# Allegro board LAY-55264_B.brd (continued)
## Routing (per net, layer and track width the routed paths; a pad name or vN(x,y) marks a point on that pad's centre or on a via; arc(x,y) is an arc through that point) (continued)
VCC_1V0_SER: length 20.6
  TOP w0.254: U1.23 31.7,51.69 v2(31.24,51.69) 30.86,51.69 TP18.1
  TOP w0.381: R22.1 16.21,65.61 18.44,63.37 v2(18.44,57.91)
  TOP w0.508: C30.1 v2(20.98,50.19) ; C30.1 v2(20.98,53.98) ; C30.1 v2(22.73,52.07)
  BOTTOM w0.381: C28.1 31.24,51.18 v2(31.24,51.69)
  BOTTOM w0.508: C29.1 v2(31.24,51.69)
  vias: v2(16.93,55.86) v2(17.7,57.1) v2(18.06,55.85) v2(19.23,56.9) v2(19.23,55.83)
VCC_1V8_LVDS: length 71.4
  TOP w0.254: U4.6 95.92,51.68 95.92,52.05 v2(95.85,52.13) ; v2(97.64,50.33) 97.4,50.33 U4.2 ; 134.24,9.02 v2(135,9.02) ; 134.24,6.48 v2(134.24,7.23) ; v2(89.11,52.92) U4.20 ; v2(98.27,49.7) 97.48,49.7 U4.1 ; U4.5 96.36,51.41 96.39,51.41 v2(96.48,51.5) ; R112.2 v2(80.25,55.88) ; U4.43 92.87,43.5 v2(92.87,42.89) 92.87,42.53 92.96,42.44 TP22.1 ; U4.44 v2(93.55,43.53) ; 134.24,3.94 v2(134.24,4.69)
  TOP w0.279: v2(134.36,45.3) 134.15,45.09 U6.39 ; U6.17 v2(138.97,38.12)
  TOP w0.381: R40.1 v2(97.13,57.36) ; R36.1 v2(78.14,48.03) ; TP23.1 98.97,50.04 98.61,50.04 v2(98.27,49.7) ; R73.2 v2(86.51,29.55) ; C50.2 v2(93.63,40.65)
  TOP w0.508: v2(129.79,12.2) 131.15,13.55 v2(131.15,13.91) 129.68,15.38 v2(127.89,15.38) 126.38,15.38 125.73,14.73 117.6,14.73 115.57,16.76 115.57,18.07 v2(114.72,18.92) ; R39.1 v2(95.73,39.95)
  L3_MIX_1 w0.508: 74.3,35.24 J6.28 ; J6.28 73.34,36.2 ; J6.28 75.25,36.2 ; J6.28 74.3,37.15 ; J6.29 72.71,33.66 ; J6.29 71.75,32.7 ; J6.29 70.8,33.66 ; J6.29 71.75,34.61 ; J6.27 71.75,37.15 ; J6.27 71.75,35.24 ; J6.27 72.71,36.2 ; J6.27 70.8,36.2 ; J6.30 74.3,34.61 ; J6.30 75.25,33.66 ; J6.30 74.3,32.7 ; J6.30 73.34,33.66 ; J12.3 71.75,29.02 ; J12.3 70.67,27.94 ; J12.3 72.84,27.94
  BOTTOM w0.381: C51.1 93.55,43.65 v2(93.55,43.53) ; C52.1 v2(92.87,42.89) ; C53.1 96.48,51.14 v2(96.48,51.5) ; C55.1 89.72,52.31 v2(89.11,52.92) ; C41.1 97.1,50.33 v2(97.64,50.33) ; R76.2 v2(98.17,26.3) ; R77.2 v2(95.81,26.3) ; C54.1 95.85,51.95 v2(95.85,52.13) ; R41.1 v2(86.69,56.44) ; C40.1 97.91,49.7 v2(98.27,49.7)
  BOTTOM w0.508: R92.2 v2(131.15,13.91) ; R46.1 v2(127.89,15.38) ; R45.1 v2(129.79,12.2)
  vias: v1(89.29,41.1) v1(90.22,40.18) v2(89.46,19.79) v2(89.46,18.92) v2(113.64,20.18) v2(132.82,52.95) v2(132.82,51.87) v2(132.82,50.61) v2(132.84,53.98) v2(132.97,55.04) v2(133.9,53.95) v2(135,55.02) v2(134.98,53.95)
VCC_1V8_MIPI: length 52.1
  TOP w0.254: R88.2 v2(53.47,40.37) ; v1(34.46,52.11) 34.11,52.11 U1.19 ; U9.5 v2(52.07,53.1) ; U1.28 30.2,49.66 29.54,49.66 v2(29.29,49.4) ; U1.9 v2(38.46,52.85)
  TOP w0.381: v2(29.29,49.4) 28.75,48.87 TP19.1 ; v2(48.13,28.22) 48.16,28.19 TP49.1 ; U2.5 31.61,34.91 31.62,34.92 v2(32.37,34.92) ; U3.1 v2(15.9,63.84) ; R100.1 v2(20.95,70.24) ; R98.1 v2(20.95,67.7) ; R108.1 v2(20.95,72.77)
  TOP w0.508: 49.3,57.97 v2(49.83,58.5) ; R23.1 v2(50.53,45.26) ; R18.1 v2(48.38,59.96) ; R24.1 v2(50.53,49.58) ; R16.1 v2(45.15,56.05)
  L3_MIX_1 w0.508: J4.27 4.44,37.15 ; J4.27 3.49,36.2 ; J4.27 5.4,36.2 ; J4.27 4.44,35.24 ; 6.98,32.7 J4.30 ; J4.30 7.94,33.66 ; J4.30 6.03,33.66 ; J4.30 6.98,34.61 ; 6.03,36.2 J4.28 ; J4.28 6.98,37.15 ; J4.28 7.94,36.2 ; J4.28 6.98,35.24 ; 4.44,32.7 J4.29 ; J4.29 5.4,33.66 ; J4.29 3.49,33.66 ; J4.29 4.44,34.61
  BOTTOM w0.381: v2(33.4,30.45) 32.88,30.98 U8.5
  BOTTOM w0.508: C21.1 35.07,52.73 35.07,52.73 v1(34.46,52.11) ; C23.1 39.01,53.41 v2(38.46,52.85) 37.91,52.31 C22.1 ; C24.1 30.14,49.4 v2(29.29,49.4) 29.29,49.41 C25.1 ; R14.1 v2(36.83,30.62)
  BOTTOM w0.635: J11.3 58.42,22.86 53.21,28.07 C1.2
  vias: v2(11.51,56.74) v2(12,57.83) v2(12.72,56.83) v2(22.87,28.04) v2(23.83,27.19) v2(48.13,27.41)
VCC_3V3_LVDS: length 54
  TOP w0.254: 143.64,33.78 v2(144.39,33.78) ; v2(144.39,32.77) 143.64,32.77
  TOP w0.279: U6.23 140.79,41.12 v2(140.97,41.3) ; U6.4 134.15,35.32 v1(133.49,34.65) ; U6.9 v2(136.65,35.52)
  TOP w0.381: U5.5 v2(79.42,45.45) ; U7.5 v2(77.2,53.58)
  TOP w0.508: D3.A v2(143.28,12.58) ; D4.A v2(143.28,10.17) ; D9.A v2(143.26,14.99) ; R74.1 v2(141.62,36.7) ; D13.A v2(143.26,17.41)
  L3_MIX_1 w0.381: v2(77.2,53.58) 77.2,47.68 v2(79.42,45.45)
  L3_MIX_1 w0.508: J12.1 71.75,23.94 ; J12.1 70.67,22.86 ; J12.1 72.84,22.86 ; J12.1 71.75,21.78
  BOTTOM w0.381: C105.1 140.18,41.3 v2(140.97,41.3) ; v2(79.42,45.45) 79.42,44.7 C42.2 79.32,42.47 77.95,41.1 77.95,33.07 74.04,29.16 74.04,23.24 73.66,22.86 J12.1
  BOTTOM w0.508: R49.1 v2(132.89,19.86)
  vias: v1(136.53,22.35) v1(142.62,39.5) v2(83.06,19.79) v2(83.06,18.92) v2(108.32,19.79) v2(108.32,18.92) v2(135.38,28.32) v2(135.38,27.3) v2(135.38,26.42) v2(135.38,25.4) v2(135.38,24.26) v2(135.38,23.24) v2(135.38,22.35) v2(136.53,28.32) v2(136.53,27.18) v2(136.53,26.29) v2(136.53,25.27) v2(136.53,24.26) v2(136.53,23.24) v2(137.67,23.24) v2(137.67,22.35) v2(138.81,23.24) v2(138.81,22.35)
VCC_3V3_MIPI: length 10.6
  TOP w0.381: v2(41.68,28.19) TP50.1
  TOP w0.508: D7.A v2(61.72,41.54) ; D14.A v2(61.72,43.96) ; D2.A v2(61.72,36.06) ; D1.A v2(61.72,38.48)
  L4_MIX_2 w0.508: 60.13,28.77 J11.1 ; J11.1 61.79,27.11 ; J11.1 60.13,27.11 ; J11.1 61.79,28.77
  BOTTOM w0.508: R28.1 v2(54.28,44.7)
  vias: v2(14.73,34.42) v2(14.73,32.26) v2(15.61,33.53) v2(41.7,27.2)
VCC_5V0_LVDS: length 7.5
  TOP w0.254: v1(135.12,34.89) 135.15,34.92 U6.6 ; U6.48 131.16,41.12 v2(130.94,40.89) ; U6.36 135.65,45.1 v2(135.89,45.34) ; v2(134.06,37.37) 133.65,36.96 U6.3 ; U6.53 v2(132.83,38.62)
  TOP w0.508: D11.A v2(143.37,19.4)
  BOTTOM w0.254: C100.1 v2(135.89,45.34)
  vias: v1(112.9,56.77) v1(135.36,33.63) v1(135.99,32.97) v2(79.07,19.79) v2(79.1,18.92) v2(104.33,19.79) v2(104.36,18.92) v2(110.97,56.77) v2(110.97,55.63) v2(110.97,54.48) v2(110.97,53.47) v2(111.89,56.77) v2(111.94,55.63) v2(112.01,54.57) v2(112.9,55.63) v2(112.9,54.23) v2(113.92,55.4) v2(114.94,55.4) v2(115.9,55.4) v2(136.3,46.63) v2(137.13,46.65)
VCC_5V0_MIPI: length 1.8
  TOP w0.508: TP51.1 37.97,27.69 38.48,27.18 v2(39.21,27.18)
  vias: v2(13.93,28.17) v2(14.94,27.19) v2(39.2,28.17)
VCC_12V0: length 5
  TOP w0.635: J9.2 122.44,73.53 ; J9.2 124.2,71.76 ; J9.2 122.44,71.76 ; J9.2 124.2,73.53
VCC_12V0_DESCONN: length 6.9
  TOP w0.635: 120.78,71.49 J9.3 ; J9.3 119.62,72.64 ; J9.3 120.78,73.8
  BOTTOM w0.635: 120.78,71.49 J9.3 ; J9.3 120.78,73.8 ; J9.3 119.62,72.64
  vias: v2(110.24,68.07) v2(110.92,67.24) v2(110.98,68.85) v2(111.76,69.6) v2(112.52,70.36) v2(113.18,69.49)
VCC_12V0_EXT: length 18
  TOP w0.508: 137.32,60.46 J10.1 ; J10.1 138.71,61.85 ; J10.1 137.32,63.23 ; J10.1 135.93,61.85
  TOP w0.635: J9.1 127.01,72.64 ; J9.1 125.86,73.8 ; J9.1 125.86,71.49
  BOTTOM w0.508: J10.1 138.71,61.85 ; J10.1 135.93,61.85 ; J10.1 137.32,60.46 ; J10.1 137.32,63.23
  BOTTOM w0.635: 125.86,71.49 J9.1 ; J9.1 125.86,73.8 ; J9.1 127.01,72.64
  vias: v2(130.18,65.15) v2(130.18,64.14) v2(130.18,62.99) v2(131.19,62.99) v2(132.46,62.99) v2(133.6,62.99)
VCC_12V0_LVDS: length 20.8
  TOP w0.381: R57.1 v2(112.66,41.27)
  TOP w0.508: D10.A v2(143.37,21.05)
  BOTTOM w0.381: v2(143.37,21.05) 142.71,21.72 132.33,21.72 131.7,21.08 130.3,21.08 129.54,21.84 v2(125.22,21.84)
  vias: v2(85.47,19.79) v2(85.5,18.92) v2(110.73,19.79) v2(110.76,18.92) v2(114.17,63.12) v2(114.17,62.1) v2(114.81,65.02) v2(114.81,64.01) v2(115.19,63.12) v2(115.19,62.1) v2(115.82,65.02) v2(115.82,64.01) v2(116.2,63.12) v2(116.2,62.1) v2(116.84,65.02) v2(116.84,64.01) v2(117.22,63.12) v2(117.22,62.1) v2(118.24,63.12) v2(118.24,62.1) v2(119.25,63.12) v2(119.25,62.1) v2(123.83,25.27) v2(123.83,24.13) v2(123.83,22.99) v2(123.83,21.84) v2(123.83,20.7) v2(125.09,25.27) v2(125.22,24.13) v2(125.22,22.99) v2(125.22,20.7) v2(126.24,25.27) v2(126.49,20.7) v2(127,28.58) v2(127,27.56) v2(127,26.54) v2(127.51,25.27)
VCC_12V0_MIPI: length 11.5
  TOP w0.381: TP52.1 20.37,27.18 v2(20.4,27.2)
  TOP w0.508: 57.47,59.56 C86.1 ; C86.1 59.88,59.56 ; C86.1 58.67,58.36 ; C86.1 58.67,60.77 ; D8.A v2(61.72,46.39)
  L3_MIX_1 w0.508: C86.1 58.67,60.69 ; C86.1 59.81,59.56 ; C86.1 58.67,58.43 ; C86.1 57.54,59.56
  vias: v2(20.41,28.19) v2(45.67,28.19) v2(45.66,27.2) v2(56.9,62.61) v2(56.9,61.47) v2(58.17,62.61) v2(58.17,61.47) v2(59.44,62.61) v2(59.44,61.47) v2(60.45,60.83) v2(60.45,59.69) v2(60.45,58.67) v2(60.58,61.98) v2(61.72,60.83) v2(61.72,59.69) v2(61.72,58.67)
VCC_12V0_SER: length 32.2
  TOP w0.254: TP16.1 v2(53.98,71.25)
  TOP w0.508: D12.A v2(60.72,49.64)
  L3_MIX_1 w0.254: v2(53.21,65.6) 54.74,67.12 54.74,70.48 v2(53.98,71.25)
  BOTTOM w0.381: v2(52.2,64.77) 52.2,56.39 51.18,55.37 51.18,51.69 51.94,50.93 59.43,50.93 v2(60.72,49.64)
  vias: v2(51.18,66.67) v2(51.18,65.71) v2(51.18,64.77) v2(51.69,67.44) v2(52.2,66.67) v2(52.2,65.71) v2(53.21,64.77)
VDDA_MAX96752: length 5
  TOP w0.254: v2(94.68,53.3) 94.68,53.27 U4.10
  TOP w0.381: TP2.1 95.25,53.72 95.1,53.72 v2(94.68,53.3)
  BOTTOM w0.381: C48.2 95.31,53.92 v2(94.68,53.3) C49.1
VDDD_MAX96752: length 5.9
  TOP w0.254: U4.56 97.6,47.97 98.06,47.97
  TOP w0.381: 98.06,47.97 99.46,47.97 C47.1 C46.2 TP1.1
FS84_DBG: length 9.6
  TOP w0.254: U6.8 v2(136.15,37.29)
  TOP w0.381: R79.2 v2(139.84,31.5)
  BOTTOM w0.381: v2(139.84,31.5) 139.84,34.53 138.43,35.94 137.5,35.94 v2(136.15,37.29)
FS84_ERRMON: length 2
  TOP w0.137: U6.40 133.65,45.25 v2(133.54,45.35)
  BOTTOM w0.137: v2(133.54,45.35) 133.6,45.42 R64.1
FS84_INTB: length 4.1
  TOP w0.137: C98.1 139.07,47.12 139.07,46.74 137.15,44.82 U6.33
FS84_PRE_BOOT: length 3.1
  TOP w0.137: C79.2 130.04,41.78 130.94,41.78 131.27,42.12 U6.46
FS84_PRE_COMP: length 3.6
  TOP w0.254: U6.41 133.15,44.95 132.84,45.26 132.84,45.72 R63.1 C85.1
FS84_PRE_CSP: length 14.1
  TOP w0.254: v2(132.23,45.14) 132.65,44.72 U6.42
  BOTTOM w0.381: v2(132.23,45.14) 132.23,45.95 125.25,52.93 v2(125.25,55.32)
FS84_PRE_GHS: length 7.8
  TOP w0.254: U6.45 131.01,42.62 130.92,42.53 v1(130.31,42.53)
  TOP w0.381: Q7.2 125.24,42.53 v2(125.6,42.16)
  BOTTOM w0.381: v1(130.31,42.53) 129.95,42.16 v2(125.6,42.16)
FS84_PRE_GLS: length 9
  TOP w0.254: v2(125.46,45.07) 125.45,45.07 Q7.4 ; U6.43 131.41,43.62 v2(131.09,43.94)
  BOTTOM w0.381: v2(131.09,43.94) 129.17,43.94 127.89,45.21 125.61,45.21 v2(125.46,45.07) 125.45,45.07 124.73,45.07 R61.1
FS84_PRE_SW: length 2.8
  TOP w0.254: C79.1 R60.1 130.74,43.12 U6.44
FS84_PSYNC: length 2.8
  TOP w0.254: U6.38 134.65,43.53 v2(134.75,43.43)
  BOTTOM w0.254: v2(134.75,43.43) C94.1 R62.2
FS84_SCL: length 5.7
  TOP w0.137: R65.2 139.52,33.83 139.52,34.38 138.77,35.13 137.72,35.13 137.15,35.7 U6.10
FS84_SDA: length 4.5
  TOP w0.137: U6.11 137.65,35.7 137.96,35.39 138.88,35.39 140.51,33.76 R66.2
FS84_VBOS: length 5.6
  TOP w0.254: U6.47 v2(132.83,41.62)
  BOTTOM w0.254: v2(132.83,41.62) 131.83,42.62 R62.1 131.83,44.2 131.44,44.58 130.94,44.58 C78.2
FS84_WAKE1: length 24.9
  TOP w0.137: C74.1 R58.2 v2(113.41,45.07) ; U6.49 v2(132.83,40.62)
  BOTTOM w0.137: v2(132.83,40.62) 131.58,39.37 126.87,39.37 121.18,45.07 v2(113.41,45.07)
GMSL2_OUT0_N: length 19.7
  TOP w0.114: C10.1 30.19,54.61 arc(30.16,54.74) 30.09,54.84 30.08,54.85 arc(29.97,54.92) 29.85,54.95 v1(29.58,54.95)
  BOTTOM w0.114: v1(29.58,54.95) 28.11,56.42 arc(27.98,56.62) 27.93,56.84 27.93,58 arc(27.7,58.56) 27.14,58.79 26.82,58.79 arc(26.13,59.08) 25.84,59.77 25.84,60.67 arc(26.11,61.31) 26.75,61.57 26.87,61.57 arc(27.61,61.88) 27.92,62.63 27.92,69.16 arc(27.79,69.48) 27.47,69.61 J3.4
GMSL2_OUT0_P: length 19.7
  TOP w0.114: C9.1 30.5,54.96 arc(30.39,54.99) 30.3,55.05 30.28,55.06 arc(30.22,55.15) 30.2,55.26 v1(30.2,55.57)
  BOTTOM w0.114: v1(30.2,55.57) 29.44,55.57 arc(29.38,55.58) 29.32,55.62 28.31,56.63 arc(28.25,56.73) 28.22,56.84 28.22,58 arc(27.91,58.77) 27.14,59.08 26.82,59.08 arc(26.34,59.28) 26.13,59.77 26.13,60.67 arc(26.32,61.1) 26.75,61.28 26.87,61.28 arc(27.82,61.68) 28.21,62.63 28.21,69.15 arc(28.35,69.48) 28.67,69.61 J3.3
GMSL2_OUT1_N: length 19.7
  TOP w0.114: v1(41.73,54.4) 41.44,54.4 arc(41.32,54.37) 41.23,54.31 41.21,54.29 arc(41.15,54.2) 41.12,54.08 C12.1
  BOTTOM w0.114: J3.1 36.63,69.61 arc(36.33,69.49) 36.21,69.2 36.21,63.21 arc(36.34,62.57) 36.7,62.03 42.1,56.63 arc(42.28,56.36) 42.35,56.04 42.35,55.21 arc(42.3,55) 42.17,54.83 v1(41.73,54.4)
GMSL2_OUT1_P: length 19.7
  TOP w0.114: C11.1 40.79,54.41 arc(40.91,54.44) 41,54.5 41.02,54.52 arc(41.08,54.61) 41.11,54.73 v1(41.11,55.02)
  BOTTOM w0.114: J3.2 35.5,69.61 arc(35.8,69.49) 35.92,69.2 35.92,63.21 arc(36.07,62.46) 36.49,61.83 41.9,56.42 arc(42.01,56.25) 42.06,56.04 42.06,55.21 arc(42,55.08) 41.86,55.02 v1(41.11,55.02)
GMSL2DES_OUT0_N: length 20.2
  TOP w0.114: v1(84.22,55.13) 84.49,55.13 arc(84.62,55.11) 84.74,55.03 85.27,54.5 arc(85.34,54.39) 85.37,54.26 C35.1
  BOTTOM w0.114: v1(84.22,55.13) 83.34,56.01 arc(83.16,56.27) 83.1,56.58 83.1,57.41 arc(82.92,57.85) 82.47,58.04 82.36,58.04 arc(81.83,58.26) 81.61,58.78 81.61,59.02 arc(81.87,59.63) 82.47,59.88 arc(82.92,60.06) 83.1,60.51 83.1,60.79 arc(83.24,61.46) 83.62,62.04 85.21,63.63 arc(85.59,64.2) 85.73,64.87 85.73,69.27 arc(85.63,69.51) 85.38,69.61 J5.4
GMSL2DES_OUT0_P: length 20.2
  TOP w0.114: v1(84.86,55.77) 84.86,55.5 arc(84.88,55.37) 84.96,55.26 85.45,54.77 arc(85.56,54.69) 85.69,54.67 C34.1
  BOTTOM w0.114: v1(84.86,55.77) 84.26,55.77 arc(84.01,55.82) 83.8,55.96 83.54,56.22 arc(83.43,56.38) 83.39,56.58 83.39,57.41 arc(83.12,58.06) 82.47,58.33 82.36,58.33 arc(82.04,58.46) 81.91,58.78 81.91,59.02 arc(82.07,59.42) 82.47,59.59 arc(83.12,59.86) 83.39,60.51 83.39,60.79 arc(83.51,61.35) 83.83,61.83 85.42,63.42 arc(85.86,64.09) 86.02,64.87 86.02,69.27 arc(86.12,69.51) 86.36,69.61 J5.3
GMSL2DES_OUT1_N: length 21.6
  TOP w0.114: v1(99.84,53.19) 99.56,53.19 arc(99.43,53.17) 99.32,53.09 99.09,52.86 arc(99.02,52.75) 98.99,52.62 C37.1
  BOTTOM w0.114: J5.1 94.19,69.61 arc(94.07,69.56) 94.02,69.44 94.02,65.81 arc(94.47,63.55) 95.75,61.64 100.35,57.03 arc(100.67,56.57) 100.78,56.01 100.78,54.52 arc(100.7,54.15) 100.49,53.84 v1(99.84,53.19)
GMSL2DES_OUT1_P: length 21.6
  TOP w0.114: C36.1 98.58,52.94 arc(98.71,52.96) 98.82,53.04 99.1,53.32 arc(99.18,53.43) 99.2,53.56 v1(99.2,53.83)
  BOTTOM w0.114: J5.2 93.61,69.61 arc(93.69,69.58) 93.73,69.5 93.73,65.81 arc(94.2,63.44) 95.54,61.43 100.15,56.83 arc(100.4,56.45) 100.48,56.01 100.48,54.52 arc(100.43,54.27) 100.29,54.05 100.17,53.93 arc(100.06,53.86) 99.93,53.83 v1(99.2,53.83)
LDO_1V0_FB_SER: length 2.8
  TOP w0.137: U3.3 12.9,64.57 R27.1 R22.2
LVDS0_BL_PWM: length 59.2
  TOP w0.137: v2(83.44,49.42) R114.2
  L4_MIX_2 w0.14: v2(84.02,28.27) 86.25,26.04 v2(87.02,26.04) 87.02,26.57 88.67,28.22 98.55,28.22 v2(100.36,26.42)
  BOTTOM w0.137: v2(84.02,28.27) 83.36,28.93 83.36,30.66 84.76,32.05 84.76,44.32 84.28,44.81 84.28,47.6 83.44,48.44 v2(83.44,49.42) ; J7.B8 v2(87.02,26.04) ; v2(100.36,26.42) 104.8,30.86 111.63,30.86 R52.2
LVDS0_CH0_CLK_N: length 36.5
  TOP w0.114: U4.35 88.56,45.73 88.41,45.73 85.23,42.55 85.23,26.44 89.57,22.11 89.73,22.11 89.88,22.25 90.04,22.25 90.2,22.09 90.2,21.93 90.05,21.78 90.05,21.62 90.21,21.46 90.37,21.46 90.52,21.61 90.68,21.61 90.85,21.45 90.85,21.28 90.7,21.14 90.7,20.97 91.16,20.51 91.16,20.07 91.67,19.55 91.93,19.55 v2(92.22,19.85)
  BOTTOM w0.114: J7.A2 91.42,20.89 91.15,20.61 91.15,19.82 91.43,19.55 91.92,19.55 v2(92.22,19.85)
LVDS0_CH0_CLK_P: length 36.5
  TOP w0.114: v2(92.22,18.97) 91.93,19.26 91.55,19.26 90.87,19.94 90.87,20.39 84.94,26.32 84.94,42.67 88.2,45.94 88.2,46.09 U4.34
  BOTTOM w0.114: v2(92.22,18.97) 91.94,19.25 91.27,19.25 90.86,19.67 90.86,20.6 90.62,20.83 J7.A3
LVDS0_CH0_TS_SCL: length 30.8
  BOTTOM w0.137: J16.3 95.28,13.3 95.28,17.7 93.68,19.3 93.68,28.04 92.79,28.93 86.16,28.93 84.62,27.4 J7.B11
LVDS0_CH0_TS_SDA: length 34.2
  BOTTOM w0.137: J7.B10 85.42,27.61 86.36,28.55 92.72,28.55 93.36,27.91 93.36,19.17 94.96,17.57 94.96,13.09 95.63,12.42 95.63,11.05 96.37,10.31 98.25,10.31 J16.4
LVDS0_CH0_TX0_N: length 36.6
  TOP w0.114: v2(91.87,27.68) 91.57,27.97 91.57,28.35 91.83,28.61 91.83,28.88 91.57,29.14 91.57,31.84 91.68,31.96 93.42,31.96 93.71,32.24 93.71,32.94 93.42,33.23 91.68,33.23 91.57,33.34 91.57,33.8 91.68,33.91 93.42,33.91 93.71,34.2 93.71,34.9 93.42,35.18 91.68,35.18 91.57,35.3 91.57,35.76 91.68,35.87 93.42,35.87 93.71,36.16 93.71,36.85 93.42,37.14 91.68,37.14 91.57,37.25 91.57,38.19 91,38.76 88.16,38.76 88.04,38.88 88.04,41.29 89.02,42.27 89.02,43.52 89.83,44.32 89.97,44.32 U4.39
  BOTTOM w0.114: v2(91.87,27.68) 91.58,27.39 91.58,25.81 91.82,25.57 J7.B2
LVDS0_CH0_TX0_P: length 36.6
  TOP w0.114: U4.38 89.62,44.67 89.62,44.52 88.73,43.64 88.73,42.39 87.75,41.41 87.75,38.76 88.04,38.47 90.87,38.47 91.28,38.07 91.28,37.13 91.56,36.85 93.3,36.85 93.41,36.73 93.41,36.28 93.3,36.16 91.56,36.16 91.28,35.88 91.28,35.18 91.56,34.89 93.3,34.89 93.41,34.78 93.41,34.32 93.3,34.21 91.56,34.21 91.28,33.92 91.28,33.22 91.56,32.94 93.3,32.94 93.41,32.82 93.41,32.36 93.3,32.25 91.56,32.25 91.28,31.97 91.28,27.97 v2(90.98,27.68)
  BOTTOM w0.114: v2(90.98,27.68) 91.29,27.37 91.29,25.83 91.02,25.57 J7.B3
LVDS0_CH0_TX1_N: length 36.5
  TOP w0.114: v2(89.47,26.66) 89.12,27.01 89.12,27.35 89.32,27.55 89.32,27.93 89.12,28.13 89.12,30.37 88.75,30.74 88.75,30.9 89.67,31.82 89.67,32.22 89.18,32.72 88.78,32.72 87.86,31.8 87.69,31.8 86.73,32.76 86.73,33.78 86.84,33.9 89.07,33.9 89.36,34.18 89.36,34.88 89.07,35.17 86.84,35.17 86.73,35.28 86.73,35.74 86.84,35.85 89.07,35.85 89.36,36.14 89.36,36.84 89.07,37.12 86.84,37.12 86.73,37.24 86.73,42.02 88.15,43.44 88.15,44.06 89.12,45.02 89.27,45.02 U4.37
  BOTTOM w0.114: v2(89.47,26.66) 89.17,26.36 89.17,25.83 89.42,25.57 J7.B5
LVDS0_CH0_TX1_P: length 36.5
  TOP w0.114: U4.36 88.91,45.38 88.91,45.23 87.86,44.18 87.86,43.56 86.44,42.14 86.44,37.12 86.72,36.83 88.95,36.83 89.07,36.72 89.07,36.26 88.95,36.14 86.72,36.14 86.44,35.86 86.44,35.16 86.72,34.87 88.95,34.87 89.07,34.76 89.07,34.3 88.95,34.19 86.72,34.19 86.44,33.9 86.44,32.64 87.57,31.5 87.98,31.5 88.9,32.42 89.06,32.42 89.38,32.1 89.38,31.94 88.46,31.02 88.46,30.62 88.83,30.25 88.83,26.91 v2(88.58,26.66)
  BOTTOM w0.114: J7.B6 88.62,25.57 88.88,25.82 88.88,26.37 v2(88.58,26.66)
LVDS0_CH0_TX2_N: length 36.5
  TOP w0.114: v2(83.07,26.66) 82.77,26.96 82.77,29.5 82.49,29.79 81.59,29.79 81.48,29.9 81.48,30.36 81.59,30.47 82.49,30.47 82.77,30.76 82.77,31.46 82.49,31.74 81.59,31.74 81.48,31.86 81.48,32.32 81.59,32.43 82.49,32.43 82.77,32.72 82.77,33.42 82.49,33.7 81.59,33.7 81.48,33.81 81.48,34.27 81.59,34.39 82.49,34.39 82.77,34.67 82.77,35.37 82.49,35.66 81.59,35.66 81.48,35.77 81.48,36.23 81.59,36.34 82.49,36.34 82.77,36.63 82.77,37.33 82.49,37.61 81.59,37.61 81.48,37.73 81.48,38.18 81.59,38.3 82.49,38.3 82.77,38.58 82.77,39.17 82.94,39.33 82.94,39.79 82.77,39.96 82.77,40.34 82.94,40.5 82.94,40.96 82.77,41.12 82.77,42.1 85.96,45.29 86.55,45.29 87.7,46.44 87.85,46.44 U4.33
  BOTTOM w0.114: J7.B13 83.02,25.57 82.78,25.82 82.78,26.37 v2(83.07,26.66)
LVDS0_CH0_TX2_P: length 36.4
  TOP w0.114: U4.32 87.5,46.79 87.5,46.65 86.43,45.58 85.83,45.58 82.48,42.22 82.48,38.7 82.36,38.59 81.47,38.59 81.18,38.3 81.18,37.61 81.47,37.32 82.36,37.32 82.48,37.21 82.48,36.75 82.36,36.63 81.47,36.63 81.18,36.35 81.18,35.65 81.47,35.36 82.36,35.36 82.48,35.25 82.48,34.79 82.36,34.68 81.47,34.68 81.18,34.39 81.18,33.69 81.47,33.41 82.36,33.41 82.48,33.29 82.48,32.84 82.36,32.72 81.47,32.72 81.18,32.44 81.18,31.74 81.47,31.45 82.36,31.45 82.48,31.34 82.48,30.88 82.36,30.77 81.47,30.77 81.18,30.48 81.18,29.78 81.47,29.5 82.36,29.5 82.48,29.38 82.48,26.96 v2(82.18,26.66)
  BOTTOM w0.114: J7.B14 82.22,25.57 82.48,25.83 82.48,26.36 v2(82.18,26.66)
LVDS0_CH0_TX3_N: length 36.5
  TOP w0.114: v2(80.67,27.68) 80.37,27.97 80.37,30.74 80.09,31.02 79.14,31.02 79.02,31.14 79.02,31.59 79.14,31.71 80.09,31.71 80.37,31.99 80.37,32.69 80.09,32.98 79.14,32.98 79.02,33.09 79.02,33.55 79.14,33.66 80.09,33.66 80.37,33.95 80.37,34.65 80.09,34.93 79.14,34.93 79.02,35.05 79.02,35.5 79.14,35.62 80.09,35.62 80.37,35.9 80.37,36.6 80.09,36.89 79.14,36.89 79.02,37 79.02,37.46 79.14,37.57 80.09,37.57 80.37,37.86 80.37,38.91 80.52,39.06 80.52,39.54 80.37,39.69 80.37,40.07 80.53,40.23 80.53,40.7 80.37,40.86 80.37,41.68 84.87,46.18 86.04,46.18 87,47.15 87.14,47.15 U4.31
  BOTTOM w0.114: J7.B16 80.62,25.57 80.37,25.83 80.37,27.38 v2(80.67,27.68)
LVDS0_CH0_TX3_P: length 36.5
  TOP w0.114: v2(79.78,27.68) 80.08,27.97 80.08,30.62 79.96,30.73 79.02,30.73 78.73,31.01 78.73,31.71 79.02,32 79.96,32 80.08,32.11 80.08,32.57 79.96,32.69 79.02,32.69 78.73,32.97 78.73,33.67 79.02,33.96 79.96,33.96 80.08,34.07 80.08,34.53 79.96,34.64 79.02,34.64 78.73,34.93 78.73,35.63 79.02,35.91 79.96,35.91 80.08,36.03 80.08,36.48 79.96,36.6 79.02,36.6 78.73,36.88 78.73,37.58 79.02,37.87 79.96,37.87 80.08,37.98 80.08,41.81 84.75,46.48 85.92,46.48 86.79,47.35 86.79,47.5 U4.30
  BOTTOM w0.114: J7.B17 79.82,25.57 80.07,25.82 80.07,27.39 v2(79.78,27.68)
LVDS0_CH1_CLK_N: length 44.2
  TOP w0.114: v2(117.49,19.85) 117.19,19.55 116.97,19.55 116.43,20.09 116.43,20.35 116.16,20.62 116.16,20.94 115.92,21.18 115.6,21.18 115.36,21.42 115.36,21.72 115.2,21.88 114.9,21.88 111.15,25.63 111.15,26.37 111.36,26.57 111.36,26.95 111.15,27.15 111.15,27.76 111.36,27.97 111.36,28.35 111.15,28.55 111.15,28.86 109.71,30.3 104.22,30.3 101.99,32.52 101.99,39.89 95.95,45.94 95.95,46.09 U4.51
  BOTTOM w0.114: J8.A2 116.69,20.94 116.41,20.66 116.41,19.79 116.66,19.55 117.19,19.55 v2(117.49,19.85)
LVDS0_CH1_CLK_P: length 44.2
  TOP w0.114: v2(117.49,18.97) 117.19,19.26 116.84,19.26 116.14,19.97 116.14,20.23 110.86,25.51 110.86,28.74 109.59,30.01 104.1,30.01 101.7,32.4 101.7,39.77 95.74,45.73 95.59,45.73 U4.50
  BOTTOM w0.114: J8.A3 115.89,20.9 116.11,20.67 116.11,19.64 116.5,19.25 117.2,19.25 v2(117.49,18.97)
LVDS0_CH1_TS_SCL: length 23.2
  BOTTOM w0.137: J15.3 98.15,19.08 100.03,19.08 103.4,22.45 103.4,26.57 105.17,28.34 109.34,28.34 109.89,27.79 J8.B11
LVDS0_CH1_TS_SDA: length 19.8
  BOTTOM w0.137: J8.B10 110.69,27.44 109.47,28.65 105.19,28.65 105.04,28.65 102.92,26.53 102.92,23.64 J15.4
LVDS0_CH1_TX0_N: length 44.2
  TOP w0.114: U4.55 97.36,47.5 97.36,47.35 98.68,46.03 100.08,46.03 106.33,39.79 106.33,39.55 106.44,39.44 107.5,39.44 107.79,39.15 107.79,38.45 107.5,38.17 106.44,38.17 106.33,38.05 106.33,37.59 106.44,37.48 107.5,37.48 107.79,37.19 107.79,36.5 107.5,36.21 106.44,36.21 106.33,36.1 106.33,35.64 106.44,35.52 107.5,35.52 107.79,35.24 107.79,34.54 107.5,34.25 106.44,34.25 106.33,34.14 106.33,33.9 107.18,33.05 113.79,33.05 116.83,30 116.83,27.97 v2(117.13,27.68)
  BOTTOM w0.114: v2(117.13,27.68) 116.84,27.38 116.84,25.82 117.09,25.57 J8.B2
LVDS0_CH1_TX0_P: length 44.3
  TOP w0.114: U4.54 97.01,47.15 97.15,47.15 98.56,45.74 99.96,45.74 106.04,39.66 106.04,39.43 106.32,39.14 107.38,39.14 107.5,39.03 107.5,38.57 107.38,38.46 106.32,38.46 106.04,38.17 106.04,37.47 106.32,37.19 107.38,37.19 107.5,37.07 107.5,36.62 107.38,36.5 106.32,36.5 106.04,36.22 106.04,35.52 106.32,35.23 107.38,35.23 107.5,35.12 107.5,34.66 107.38,34.55 106.32,34.55 106.04,34.26 106.04,33.78 107.06,32.75 113.67,32.75 114.89,31.53 114.89,31.28 115.2,30.97 115.45,30.97 115.72,30.7 115.72,30.46 116.03,30.15 116.27,30.15 116.54,29.88 116.54,27.97 v2(116.25,27.68)
  BOTTOM w0.114: J8.B3 116.29,25.57 116.54,25.83 116.54,27.38 v2(116.25,27.68)
LVDS0_CH1_TX1_N: length 44.1
  TOP w0.114: v2(114.73,26.66) 114.43,26.96 114.43,28.76 111.58,31.62 104.72,31.62 103.28,33.06 103.28,34.24 103.39,34.36 104.7,34.36 104.99,34.64 104.99,35.34 104.7,35.63 103.39,35.63 103.28,35.74 103.28,36.2 103.39,36.31 104.7,36.31 104.99,36.6 104.99,37.3 104.7,37.58 103.39,37.58 103.28,37.7 103.28,38.16 103.39,38.27 104.7,38.27 104.99,38.55 104.99,39.25 104.7,39.54 103.39,39.54 103.28,39.65 103.28,40.78 98.9,45.15 98.14,45.15 96.65,46.65 96.65,46.79 U4.53
  BOTTOM w0.114: v2(114.73,26.66) 114.43,26.36 114.43,25.83 114.69,25.57 J8.B5
LVDS0_CH1_TX1_P: length 44.1
  TOP w0.114: U4.52 96.3,46.44 96.45,46.44 98.02,44.86 98.78,44.86 102.98,40.66 102.98,39.53 103.27,39.25 104.58,39.25 104.7,39.13 104.7,38.68 104.58,38.56 103.27,38.56 102.98,38.28 102.98,37.58 103.27,37.29 104.58,37.29 104.7,37.18 104.7,36.72 104.58,36.61 103.27,36.61 102.98,36.32 102.98,35.62 103.27,35.34 104.58,35.34 104.7,35.22 104.7,34.76 104.58,34.65 103.27,34.65 102.98,34.36 102.98,32.94 104.6,31.32 111.46,31.32 112.11,30.68 112.11,30.43 112.42,30.12 112.67,30.12 112.93,29.85 112.93,29.61 113.25,29.29 113.49,29.29 114.14,28.64 114.14,26.96 v2(113.85,26.66)
  BOTTOM w0.114: v2(113.85,26.66) 114.14,26.37 114.14,25.82 113.89,25.57 J8.B6
LVDS0_CH1_TX2_N: length 44.3
  TOP w0.114: U4.49 95.24,45.38 95.24,45.23 96.66,43.81 96.66,43.25 98.97,40.94 98.97,38.75 99.09,38.64 100.52,38.64 100.8,38.35 100.8,37.65 100.52,37.37 99.09,37.37 98.97,37.25 98.97,36.8 99.09,36.68 100.52,36.68 100.8,36.4 100.8,35.7 100.52,35.41 99.09,35.41 98.97,35.3 98.97,34.84 99.09,34.73 100.52,34.73 100.8,34.44 100.8,33.74 100.52,33.46 99.09,33.46 98.97,33.34 98.97,32.88 99.09,32.77 100.52,32.77 100.8,32.48 100.8,31.78 100.52,31.5 99.09,31.5 98.97,31.39 98.97,30.63 100.57,29.03 107.7,29.03 108.03,28.7 108.03,27.97 v2(108.33,27.68)
  BOTTOM w0.114: v2(108.33,27.68) 108.05,27.4 108.05,25.82 108.29,25.59 J8.B13
LVDS0_CH1_TX2_P: length 44.2
  TOP w0.114: v2(107.45,27.68) 107.74,27.97 107.74,28.57 107.58,28.74 107.2,28.74 106.97,28.52 106.63,28.52 106.41,28.74 100.45,28.74 98.68,30.51 98.68,31.51 98.96,31.79 100.4,31.79 100.51,31.91 100.51,32.36 100.4,32.48 98.96,32.48 98.68,32.76 98.68,33.46 98.96,33.75 100.4,33.75 100.51,33.86 100.51,34.32 100.4,34.43 98.96,34.43 98.68,34.72 98.68,35.42 98.96,35.7 100.4,35.7 100.51,35.82 100.51,36.27 100.4,36.39 98.96,36.39 98.68,36.67 98.68,37.37 98.96,37.66 100.4,37.66 100.51,37.77 100.51,38.23 100.4,38.34 98.96,38.34 98.68,38.63 98.68,40.82 96.37,43.13 96.37,43.69 95.03,45.03 94.88,45.03 U4.48
  BOTTOM w0.114: J8.B14 107.49,25.57 107.76,25.84 107.76,27.37 v2(107.45,27.68)
LVDS0_CH1_TX3_N: length 44
  TOP w0.114: v2(105.93,26.66) 105.63,26.96 105.63,27.39 105.19,27.83 98.81,27.83 97.67,28.97 97.67,29.97 97.39,30.26 95.75,30.26 95.64,30.37 95.64,30.83 95.75,30.95 97.39,30.95 97.67,31.23 97.67,31.93 97.39,32.22 95.75,32.22 95.64,32.33 95.64,32.79 95.75,32.9 97.39,32.9 97.67,33.19 97.67,33.89 97.39,34.17 95.75,34.17 95.64,34.29 95.64,34.74 95.75,34.86 97.39,34.86 97.67,35.14 97.67,35.84 97.39,36.13 95.75,36.13 95.64,36.24 95.64,36.7 95.75,36.81 97.39,36.81 97.67,37.1 97.67,40.2 95.73,42.15 95.73,43.33 94.53,44.52 94.53,44.67 U4.47
  BOTTOM w0.114: v2(105.93,26.66) 105.63,26.36 105.63,25.83 105.89,25.57 J8.B16
LVDS0_CH1_TX3_P: length 44.1
  TOP w0.114: v2(105.05,26.66) 105.34,26.96 105.34,27.27 105.07,27.54 104.69,27.54 104.51,27.36 104.08,27.36 103.9,27.54 103.3,27.54 103.14,27.39 102.66,27.39 102.51,27.54 98.69,27.54 97.38,28.85 97.38,29.85 97.27,29.97 95.63,29.97 95.35,30.25 95.35,30.95 95.63,31.24 97.27,31.24 97.38,31.35 97.38,31.81 97.27,31.92 95.63,31.92 95.35,32.21 95.35,32.91 95.63,33.19 97.27,33.19 97.38,33.31 97.38,33.76 97.27,33.88 95.63,33.88 95.35,34.16 95.35,34.86 95.63,35.15 97.27,35.15 97.38,35.26 97.38,35.72 97.27,35.83 95.63,35.83 95.35,36.12 95.35,36.82 95.63,37.1 97.27,37.1 97.38,37.22 97.38,40.08 95.44,42.02 95.44,43.2 94.32,44.32 94.18,44.32 U4.46
  BOTTOM w0.114: v2(105.05,26.66) 105.34,26.37 105.34,25.82 105.09,25.57 J8.B17
LVDS0_TS_INT: length 74.1
  TOP w0.137: R33.2 v2(96.31,57.98)
  L4_MIX_2 w0.14: v2(102.23,26.42) 101.22,26.42 98.69,28.94 87.67,28.94 v1(86.51,27.79) 85.78,27.79 v2(83.95,29.62)
  BOTTOM w0.137: v2(102.23,26.42) 102.23,27.28 105.44,30.48 111,30.48 R53.2 ; J7.B9 86.22,26.47 86.51,26.76 v1(86.51,27.79) ; v2(83.95,29.62) 83.95,30.73 84.96,31.75 84.96,31.81 85.07,31.92 85.07,44.45 84.59,44.94 84.59,46.72 88.61,50.74 88.61,53.41 90.74,55.53 90.74,57.65 91.07,57.98 v2(96.31,57.98)
LVDS_EN_1: length 69.2
  TOP w0.137: R30.1 84.22,20.93 v2(84.22,20.09) 84.22,16.58 82.52,14.88 76.73,14.88 75.44,16.18 v2(75.44,16.81) ; R110.1 80.37,57.91 81.28,57 81.28,52.81 v2(82.17,51.92) 83.48,53.24 R78.2
  BOTTOM w0.137: v2(75.44,16.81) 75.44,29.31 81.53,35.41 81.53,50.38 82.01,50.85 83.31,50.85 83.59,51.13 83.59,51.66 83.33,51.92 v2(82.17,51.92) ; J7.A11 v2(84.22,20.09)
LVDS_EN_2: length 91.7
  TOP w0.137: R111.1 80.9,56.52 80.9,52.43 81.97,51.35 v2(83.03,51.35) 83.36,51.68 83.36,51.82 R80.2 ; v2(74.83,15.82) 74.83,15.75 76.01,14.57 88.68,14.57 93.8,9.45 94.67,9.45 96.44,7.67 100,7.67 101.6,9.27 102.49,9.27 109.47,16.26 R97.1 R54.1
  BOTTOM w0.137: v2(74.83,15.82) 74.83,29.15 81.22,35.54 81.22,50.51 82.06,51.35 v2(83.03,51.35)
MAX96752_ERR_B: length 105.4
  TOP w0.137: U4.14 93.79,55.2 v2(93.79,55.2) ; v2(125.86,16.13) 125.86,17.08 122.44,20.49 122.44,20.69 122.43,20.7 122.43,25.78 113.9,34.32 112.62,34.32 110.46,36.48 110.46,38.15 109.26,39.34 109.26,43.83 101.91,51.18 v2(100.97,51.18)
  L4_MIX_2 w0.14: J6.25 73.15,37.34 78.08,37.34 79.17,36.25 95.61,36.25 103.35,43.99 103.35,51.21 102.74,51.82 101.6,51.82 v2(100.97,51.18) 100.08,51.18 98.09,53.16 98.09,53.87 95.69,56.28 94.75,56.28 94.27,55.81 94.27,55.69 v2(93.79,55.2)
  BOTTOM w0.137: R51.1 v2(125.86,16.13)
MAX96752_GPIO01_I2CSEL: length 25.1
  TOP w0.137: v1(88.03,55.09) 88.39,54.73 88.39,54.35 U4.19
  L4_MIX_2 w0.14: v1(88.03,55.09) 86.75,53.81 83.27,53.81 77.09,59.99 77.09,61.07 75.29,62.86 73.02,62.86 J6.7
MAX96752_GPIO02_MS: length 37.4
  TOP w0.137: U4.45 94.42,43.37 v2(94.42,42.13) R39.2
  L4_MIX_2 w0.14: v2(94.42,42.13) 94.13,42.41 94.13,43.48 94.05,43.57 94.05,43.74 93.75,44.04 93.58,44.04 92.68,44.93 91.59,44.93 88.65,47.88 88.65,51.99 87.46,53.17 83.01,53.17 81.56,54.62 80.25,54.62 76.95,57.92 72.89,57.92 J6.9
  BOTTOM w0.137: R39.2 94.42,41.67 v2(94.42,42.13)
MAX96752_GPIO03: length 2.9
  TOP w0.137: R34.1 90.31,42.76 89.94,43.12 89.94,43.58 U4.40
MAX96752_GPIO04: length 27.9
  TOP w0.137: U4.41 v2(90.46,43.39)
  L4_MIX_2 w0.14: J6.13 72.9,55.12 78.77,55.12 79.95,53.94 81.35,53.94 82.75,52.54 86.02,52.54 87.63,50.93 87.63,47.78 90.46,44.95 v2(90.46,43.39)
MAX96752_GPIO05: length 2.9
  TOP w0.137: R35.1 91.25,41.21 91.25,41.94 91.06,42.12 91.06,43.29 U4.42
MAX96752_GPIO06: length 20.2
  TOP w0.137: U4.27 v2(86.72,50.36)
  L4_MIX_2 w0.14: v2(86.72,50.36) 85.69,50.36 85.28,49.95 85.28,47.56 82.45,44.73 78.83,44.73 78.34,45.22 72.89,45.22 J6.19
MAX96752_GPIO07: length 21.5
  TOP w0.137: U4.28 86.59,49.78 86.36,49.78 v2(85.98,49.4)
  L4_MIX_2 w0.14: v2(85.98,49.4) 86.43,49.4 86.74,49.09 86.74,46.23 84.92,44.41 78.7,44.41 78.21,44.91 72.85,44.91 J6.21
MAX96752_GPIO08: length 34.1
  TOP w0.137: v2(84.45,48.13) 86.11,48.13 86.31,47.92 86.51,47.92 U4.29
  L4_MIX_2 w0.14: v2(84.45,48.13) 83.11,46.79 76.38,46.79 75.56,47.6 71.07,47.6 70.31,48.36 70.31,59.44 71.37,60.5 73.2,60.5 J6.8
MAX96752_GPIO09_CXTP: length 29
  TOP w0.137: U4.11 95.19,54.49 v2(95.19,55.43) R40.2
  L4_MIX_2 w0.14: v2(95.19,55.43) 95.19,55.01 93.68,53.49 83.14,53.49 81.69,54.94 80.44,54.94 76.33,59.05 J6.10
  BOTTOM w0.137: R43.1 95.74,55.97 v2(95.19,55.43)
MAX96752_GPIO10: length 31
  TOP w0.137: v2(95.07,58.48) R33.1 94.41,56.08 94.41,54.41 U4.12
  BOTTOM w0.137: v2(95.07,58.48) 91.12,58.48 90.42,57.78 90.42,55.67 88.53,53.77 79.25,53.77 76.5,56.52 J6.12
MAX96752_GPIO11: length 16.9
  TOP w0.137: U4.24 87.94,51.26 87.8,51.26 87.24,51.82 v2(85.82,51.82) 85.5,52.15 R78.1
  L4_MIX_2 w0.14: J6.14 75.12,54.8 78.64,54.8 79.82,53.62 81.22,53.62 82.62,52.22 85.42,52.22 v2(85.82,51.82)
MAX96752_GPIO12: length 16.1
  TOP w0.137: v2(84.81,50.91) 84.78,50.95 R80.1 85.3,51.28 87.21,51.28 U4.25
  L4_MIX_2 w0.14: J6.18 75.92,50.52 84.43,50.52 v2(84.81,50.91)
MAX96752_GPIO13: length 17.8
  TOP w0.137: U4.26 87.3,50.49 87.3,50.57 86.94,50.93 85.88,50.93 85.12,50.16 R114.1 v2(84.45,49.42)
  L4_MIX_2 w0.14: v2(84.45,49.42) 84.96,48.91 84.96,47.69 83.62,46.35 J6.20
MAX96752_GPIO14: length 36
  TOP w0.137: v2(96.94,52.77) 96.8,52.63 96.35,52.63 96.34,52.62 95.44,52.62 U4.8
  BOTTOM w0.137: v2(96.94,52.77) 99.09,50.62 99.09,47.74 92.77,41.42 92.77,34.29 99.19,27.88 R118.1
MAX96752_GPIO15: length 35.2
  TOP w0.137: U4.9 95.19,53.07 v2(96.16,53.07)
  BOTTOM w0.137: R119.1 96.95,29.67 92.46,34.16 92.46,41.55 98.77,47.87 98.77,50.15 96.16,52.76 v2(96.16,53.07)
MAX96752_LOCK: length 111.7
  TOP w0.137: U4.13 v2(93.6,54.31) ; v2(131.08,12.45) 131.7,13.07 131.7,14.48 129.67,16.51 126.87,16.51 122.76,20.62 122.76,26 114.12,34.63 112.75,34.63 110.77,36.61 110.77,38.35 109.65,39.47 109.65,44.15 v2(102.51,51.28)
  L4_MIX_2 w0.14: J6.23 73.15,39.88 76.28,39.88 79.53,36.63 95.54,36.63 103,44.09 103,50.8 v2(102.51,51.28) 101.96,51.28 101.28,50.61 100.2,50.61 97.78,53.03 97.78,53.74 95.56,55.96 94.88,55.96 94.59,55.68 94.59,55.3 v2(93.6,54.31)
  BOTTOM w0.137: R50.1 v2(131.08,12.45)
MAX96752_PWDN_B: length 18.2
  TOP w0.254: v2(79.92,47.31) R36.2 80.19,45.97 80.84,46.62 80.84,46.64 C45.1 ; U4.23 v2(87.99,51.92)
  BOTTOM w0.254: v2(87.99,51.92) 87,52.91 81.76,52.91 79.48,50.62 79.48,47.75 v2(79.92,47.31)
MAX96752_SCL: length 13.1
  L4_MIX_2 w0.14: J16.1 95.23,15.89 95.23,21.22 95.73,21.71 95.91,21.71 J15.1
  BOTTOM w0.137: R77.1 R119.2 96.95,22.82 J15.1
MAX96752_SCL1: length 34.7
  TOP w0.137: J16.5 95.55,10.48 95.55,16.27 J15.5
  BOTTOM w0.137: J15.5 94.82,19.87 94.82,28.93 91.24,32.51 v1(91.24,40.18)
MAX96752_SDA: length 13.2
  L4_MIX_2 w0.14: J15.2 100.49,21.82 100.68,21.82 101.42,21.09 101.42,16.02 J16.2
  BOTTOM w0.137: R76.1 R118.2 99.19,23.12 J15.2
MAX96752_SDA1: length 43.9
  TOP w0.137: J16.6 101.12,10.65 101.12,16.11 J15.6
  BOTTOM w0.137: v1(90.31,41.1) 89.74,41.66 89.06,41.66 88.73,41.33 88.73,39.93 90.91,37.74 90.91,32.4 94.5,28.8 94.5,19.74 95.71,18.54 95.71,16.84 96.17,16.38 98.2,16.38 J15.6
MAX96752_SIOA_N: length 3.7
  TOP w0.114: U4.22 89.09,51.53 88.62,51.99 arc(88.6,52.03) 88.59,52.07 88.59,52.13 arc(88.58,52.17) 88.56,52.21 88.48,52.29 arc(88.23,52.46) 87.93,52.52 arc(87.34,52.65) 86.84,52.99 86.7,53.13 arc(86.59,53.2) 86.45,53.23 C35.2
MAX96752_SIOA_P: length 3.7
  TOP w0.114: U4.21 88.98,52.35 arc(88.94,52.37) 88.9,52.38 88.84,52.38 arc(88.8,52.39) 88.76,52.41 88.68,52.49 arc(88.34,52.72) 87.94,52.81 arc(87.46,52.92) 87.05,53.19 86.9,53.34 arc(86.83,53.45) 86.8,53.58 C34.2
MAX96752_SIOB_N: length 2.4
  TOP w0.114: C37.2 97.86,51.5 arc(97.73,51.47) 97.61,51.4 97.05,50.83 arc(97.02,50.79) 97.01,50.73 97.01,50.71 arc(96.99,50.65) 96.96,50.6 U4.3
MAX96752_SIOB_P: length 2.4
  TOP w0.114: U4.4 96.59,50.94 arc(96.66,50.98) 96.74,51 arc(96.79,51.01) 96.84,51.04 97.45,51.65 arc(97.53,51.76) 97.55,51.89 97.55,52.22
MAX96752_X1: length 7.3
  TOP w0.137: U4.15 91.19,54.38 91.19,54.73 91.45,54.99 91.82,54.99 C43.1 93.34,56.52 93.34,58.57 92.42,59.5 X2.1
MAX96752_X2: length 4.4
  TOP w0.137: U4.16 90.8,54.05 C44.1 90.11,56.57 X2.3
MAX96752_XRES: length 3.6
  TOP w0.137: R38.1 88.75,54.69 U4.18
MAX96789_CAPVDD1: length 4.7
  TOP w0.254: U1.6 v2(39.58,51.86)
  TOP w0.508: TP20.1 v2(43.13,51.74) 42.44,52.43 C17.2 v2(41.78,51.81)
  BOTTOM w0.508: v2(39.58,51.86) 39.54,51.86 C16.1
MAX96789_CAPVDD2: length 7.8
  TOP w0.254: U1.22 v2(31.78,52.32)
  TOP w0.508: TP21.1 24.26,54.1 24.89,54.1 25.38,53.61 v2(26.75,53.61) C15.2 v2(28.08,53.71)
  BOTTOM w0.381: C14.1 32.28,51.82 v2(31.78,52.32)
MAX96789_CFG0: length 67
  TOP w0.137: v2(45.21,53.47) 45.21,53.49 R19.1 R16.2 ; v2(38.1,53.47) 38.1,53.2 U1.10
  L4_MIX_2 w0.14: v2(38.1,53.47) 39.24,53.47 40.07,52.64 43.11,52.64 44.2,53.72 44.96,53.72 v2(45.21,53.47) 45.97,53.47 47.5,51.94 47.5,49.45 46.47,48.43 43.74,48.43 42.99,47.68 40.8,47.68 36.76,43.65 30.53,43.65 29.54,42.66 17.41,42.66 7.49,52.58 5.84,52.58 J4.13
MAX96789_CFG1: length 93.2
  TOP w0.137: 37.13,52.94 37.52,53.33 37.52,53.62 37.89,54 38.18,54 41.12,56.94 42.05,56.94 42.81,57.71 46.25,57.71 47.17,56.79 48.12,56.79 R17.2 R20.1 v2(49.3,55.78)
  L4_MIX_2 w0.14: v2(49.3,55.78) 48.96,55.43 48.96,46.72 40.91,38.67 13.65,38.67 9.91,34.92 3.56,34.92 2.54,35.94 2.54,49.53 J4.15
MAX96789_CFG2: length 86.8
  TOP w0.137: v2(47.32,57.46) R21.1 R18.2 46.45,58.02 42.68,58.02 41.92,57.26 40.98,57.26 38.14,54.41 37.9,54.41 U1.12
  L4_MIX_2 w0.14: J4.17 2.92,47.37 2.92,38.15 3.72,37.34 8.69,37.34 10.72,39.37 40.97,39.37 48.64,47.04 48.64,56.13 v2(47.32,57.46)
MAX96789_ERRB: length 65.8
  TOP w0.137: U1.3 40.39,50.55 42.18,50.55 43.1,49.63 43.11,49.63 43.15,49.6 44.52,49.6 v2(45.72,50.8) 46.86,50.8 48.08,49.58 R31.1
  L4_MIX_2 w0.14: v2(45.72,50.8) 45.19,50.27 41.21,50.27 35.87,44.92 27.29,44.92 25.93,46.29 17.47,46.29 10.41,53.34 10.41,58.93 8.8,60.54 8.8,61.46 7.44,62.81 5.66,62.81 J4.7
MAX96789_I2C-SCL: length 68.5
  TOP w0.137: U1.14 v2(37.07,55) ; R12.1 J4.26
  L4_MIX_2 w0.14: v2(37.07,55) 37.43,55.37 38.36,55.37 40.45,53.27 42.7,53.27 43.97,54.55 45.86,54.55 48.13,52.27 48.13,47.17 40.75,39.79 10.15,39.79 9.09,38.73 J4.26
MAX96789_I2C-SDA: length 66.2
  TOP w0.137: U1.13 v2(37.02,54.25) ; R10.1 J4.24
  L4_MIX_2 w0.14: v2(37.02,54.25) 38.97,54.25 40.26,52.96 42.84,52.96 44.12,54.23 45.66,54.23 47.82,52.07 47.82,47.49 40.67,40.34 9.55,40.34 8.61,41.27 J4.24
MAX96789_LMN0: length 39.2
  TOP w0.137: v2(24.51,57.15) 24.77,56.9 28.88,56.9 R4.2 ; U1.31 v2(30.45,46.97)
  L4_MIX_2 w0.14: v2(24.51,57.15) 23.88,56.52 22.73,56.52 20.15,59.09 17.41,59.09 15.81,57.5 15.81,52.03 20.88,46.97 v2(30.45,46.97)
MAX96789_LMN1: length 40.6
  TOP w0.137: U1.32 30.39,46.2 v2(30.02,46.2) ; v2(23.37,57.28) 24.08,56.57 27.96,56.57 R3.2
  L4_MIX_2 w0.14: v2(30.02,46.2) 29.36,46.2 28.94,46.63 20.43,46.63 15.24,51.82 15.24,57.38 17.27,59.41 21.23,59.41 v2(23.37,57.28)
MAX96789_LMN2: length 22.9
  TOP w0.137: v2(44.07,57.02) 43.11,57.02 R2.2 ; U1.53 v2(40.42,46.51)
  BOTTOM w0.137: v2(40.42,46.51) 41.34,45.59 41.91,45.59 42.1,45.79 45.32,45.79 47.61,48.07 47.61,52.67 44.42,55.85 44.42,56.67 v2(44.07,57.02)
MAX96789_LMN3: length 19.6
  TOP w0.137: U1.54 41.48,46.16 v2(41.51,46.16) ; v2(43.88,55.87) 43.21,55.87 R1.2
  BOTTOM w0.137: v2(41.51,46.16) 45.25,46.16 47.3,48.2 47.3,52.45 v2(43.88,55.87)
MAX96789_MFP2: length 63.4
  TOP w0.137: v2(46.16,51.63) 45.83,51.63 44.15,49.95 43.23,49.95 42.25,50.93 40.07,50.93 U1.4
  L4_MIX_2 w0.14: v2(46.16,51.63) 46.74,51.05 46.74,49.71 46.2,49.17 43.42,49.17 42.71,48.46 40.54,48.46 36.36,44.28 27.04,44.28 26.49,43.74 25.53,43.74 25,44.27 17.07,44.27 8.66,52.68 8.66,56.59 7.34,57.91 5.59,57.91 J4.9
MAX96789_MFP3: length 64.2
  TOP w0.137: v2(45.59,52.32) 45.59,51.84 44.02,50.26 43.36,50.26 42.35,51.27 39.71,51.27 U1.5
  L4_MIX_2 w0.14: J4.11 5.71,55.24 7.67,55.24 8.31,54.61 8.31,52.4 16.84,43.87 24.64,43.87 25.45,43.05 29.46,43.05 30.37,43.96 36.55,43.96 40.67,48.08 42.9,48.08 43.59,48.77 46.31,48.77 47.12,49.58 47.12,51.56 46.35,52.32 v2(45.59,52.32)
MAX96789_MFP7: length 31.1
  TOP w0.137: U1.24 31.86,50.82 31.45,51.23 29.54,51.23 R82.1 28.16,51.82 26.96,53.01 v2(24.69,53.01)
  BOTTOM w0.137: v2(24.69,53.01) 19.2,47.52 5.62,47.52 5.13,47.03 5.12,47.03 J4.19
MAX96789_MFP8: length 31.5
  TOP w0.137: v2(25.88,52.43) 25.88,52.42 27.3,51 R81.1 28.85,51 28.96,50.9 31.08,50.9 U1.25
  BOTTOM w0.137: v2(25.88,52.43) 24.72,52.43 19.5,47.21 9.69,47.21 7.57,45.09 5.73,45.09 5.13,44.49 5.12,44.49 J4.21
MAX96789_MFP9: length 32.4
  TOP w0.137: U1.26 30.73,50.55 29.01,50.55 28.65,50.19 R5.1 26.46,50.19 v2(24.96,51.69)
  BOTTOM w0.137: v2(24.96,51.69) 20.17,46.89 11.28,46.89 9.6,45.21 9.6,44.55 7.6,42.55 5.74,42.55 5.14,41.95 5.12,41.95 J4.23
MAX96789_MFP10: length 34
  TOP w0.137: U1.27 30.37,50.19 29.11,50.19 28.77,49.85 27.88,49.85 27.56,49.53 26.63,49.53 R6.1 v2(16.26,49.17)
  L4_MIX_2 w0.14: v2(16.26,49.17) 15.44,49.98 15.44,50.48 10.95,54.97 10.95,58.93 9.22,60.66 9.22,61.9 J4.6
MAX96789_MFP11: length 34.3
  TOP w0.137: U1.29 30.02,47.96 29.46,47.96 28.98,47.48 R8.1 27.41,47.48 v2(25.72,45.78)
  L4_MIX_2 w0.14: J4.8 9.98,58.6 9.98,53.14 17.34,45.78 v2(25.72,45.78)
MAX96789_MFP12: length 33.8
  TOP w0.137: U1.30 30.2,47.43 29.77,47.43 R7.1 28.48,46.9 v2(25.92,44.34)
  L4_MIX_2 w0.14: v2(25.92,44.34) 25.55,44.7 17.27,44.7 9.09,52.88 9.09,56.95 J4.10
MAX96789_MFP17: length 44.2
  TOP w0.137: U1.55 v2(41.16,47.18) ; R9.1 J4.20
  L4_MIX_2 w0.14: v2(41.16,47.18) 41.16,46.55 35.84,41.22 15.32,41.22 13.78,42.76 10.58,42.76 J4.20
MAX96789_MFP18: length 46.9
  TOP w0.137: v2(43.1,46.96) 42.21,47.86 41.19,47.86 U1.56 ; R11.1 J4.22
  L4_MIX_2 w0.14: J4.22 8.81,43.81 10.19,42.44 13.65,42.44 15.3,40.79 37.19,40.79 43.1,46.71 v2(43.1,46.96)
MAX96789_MS_LOCK: length 71.8
  TOP w0.137: R29.1 47.75,46.15 47.75,49.28 46.99,50.04 v2(46.23,50.04) 45.45,49.26 43.02,49.26 42.12,50.16 40.72,50.16 U1.2
  L4_MIX_2 w0.14: J4.5 3.17,62.87 3.17,60.96 3.81,60.32 7.52,60.32 9.47,58.37 9.47,53.14 17.27,45.34 17.45,45.16 26.52,45.16 27.08,44.6 36.12,44.6 40.39,48.87 42.55,48.87 43.21,49.54 45.73,49.54 v2(46.23,50.04)
MAX96789_PWDN_B: length 22.9
  TOP w0.137: U1.1 41.07,49.81 41.44,49.81 v2(41.77,49.47)
  BOTTOM w0.137: v2(41.77,49.47) 41.77,48.65 39.22,46.1 39.22,33.09 C27.1 37.5,32.1 37.21,32.38 R14.2 R15.2
MAX96789_SIOA_N: length 2.8
  TOP w0.114: U1.21 32.44,52.37 arc(32.41,52.42) 32.4,52.47 32.4,52.5 arc(32.39,52.55) 32.35,52.6 31.59,53.36 arc(31.41,53.48) 31.19,53.53 C10.2
MAX96789_SIOA_P: length 2.8
  TOP w0.114: U1.20 32.8,52.72 arc(32.75,52.75) 32.69,52.76 32.67,52.76 arc(32.61,52.78) 32.56,52.81 31.79,53.58 arc(31.67,53.76) 31.62,53.98 C9.2
MAX96789_SIOB_N: length 2.5
  TOP w0.114: U1.7 39.03,52.01 arc(39.07,52.06) 39.08,52.12 39.08,52.14 arc(39.09,52.2) 39.12,52.25 39.68,52.81 arc(39.87,52.93) 40.09,52.98 C12.2
MAX96789_SIOB_P: length 2.5
  TOP w0.114: C11.2 39.69,53.45 arc(39.65,53.24) 39.53,53.07 38.91,52.46 arc(38.87,52.42) 38.81,52.41 38.78,52.41 arc(38.73,52.4) 38.68,52.37 U1.8
MAX96789_XRES: length 1.5
  TOP w0.137: R13.1 33.49,53.76 33.49,53.44 33.99,52.94
MIPI_DSI0_1_EN: length 46
  TOP w0.137: U2.1 31.61,29.76 v2(31.36,29.51)
  L4_MIX_2 w0.14: v2(31.36,29.51) 30.78,30.1 24.38,30.1 23.37,29.08 19.57,29.08 v2(18.68,28.19)
  BOTTOM w0.137: v1(28.24,52.53) 27.3,51.6 27.3,50.75 26.29,49.73 26.29,45.64 26.62,45.31 26.62,34.26 v2(31.36,29.51) ; J1.B11 19.43,27.68 19.43,27.68 R71.1 v2(18.68,28.19)
MIPI_DSI0_BL_PWM: length 50.4
  TOP w0.137: R8.2 v2(26.82,46.13)
  L4_MIX_2 w0.14: v2(20.65,19.79) 21.25,19.19 21.25,17.96 21.94,17.26 26.13,17.26 28.17,19.3 33.8,19.3 34.87,20.37 34.87,20.77 v2(35.69,21.59)
  BOTTOM w0.137: v2(26.82,46.13) 27.14,45.81 27.14,34.47 35.69,25.93 v2(35.69,21.59) ; J1.A8 21.43,20.57 v2(20.65,19.79)
MIPI_DSI0_CLK_N: length 43.3
  TOP w0.114: U1.40 33.81,43.96 33.66,43.96 32.56,42.86 32.56,38.91 30.25,36.59 30.25,35.75 29.97,35.46 28.52,35.46 28.41,35.35 28.41,34.89 28.52,34.77 29.97,34.77 30.25,34.49 30.25,33.79 29.97,33.5 28.52,33.5 28.41,33.39 28.41,32.93 28.52,32.82 29.97,32.82 30.25,32.53 30.25,31.83 29.97,31.55 28.52,31.55 28.41,31.43 28.41,30.98 28.52,30.86 29.97,30.86 30.25,30.58 30.25,28.66 32.02,26.89 32.02,24.7 31.41,24.09 28.73,24.09 28.45,24.38 28.45,25.67 28.17,25.96 28.17,26.23 28.45,26.51 28.45,26.74 28.27,26.92 27.72,26.92 v2(27.43,26.62)
  BOTTOM w0.114: J1.B2 26.63,25.58 26.38,25.83 26.38,26.71 26.61,26.94 27.11,26.94 v2(27.43,26.62)
MIPI_DSI0_CLK_P: length 43.3
  TOP w0.114: 33.99,44.85 33.46,44.32 33.46,44.17 32.27,42.99 32.27,39.03 29.96,36.72 29.96,35.87 29.84,35.75 28.4,35.75 28.12,35.47 28.12,34.77 28.4,34.48 29.84,34.48 29.96,34.37 29.96,33.91 29.84,33.8 28.4,33.8 28.12,33.51 28.12,32.81 28.4,32.53 29.84,32.53 29.96,32.41 29.96,31.95 29.84,31.84 28.4,31.84 28.12,31.56 28.12,30.86 28.4,30.57 29.84,30.57 29.96,30.46 29.96,28.54 31.73,26.77 31.73,24.82 31.29,24.38 28.86,24.38 28.74,24.5 28.74,26.86 28.39,27.21 27.72,27.21 v2(27.43,27.5)
  BOTTOM w0.114: J1.B3 25.83,25.58 26.08,25.83 26.08,26.83 26.48,27.23 27.15,27.23 v2(27.43,27.5)
MIPI_DSI0_DATA0_N: length 43.2
  TOP w0.114: v2(26.27,19.81) 25.98,20.1 25.98,20.87 26.13,21.02 26.13,21.43 25.98,21.58 25.98,21.97 26.13,22.12 26.13,22.53 25.98,22.68 25.98,23.79 25.69,24.07 23.98,24.07 23.86,24.19 23.86,24.65 23.98,24.76 25.69,24.76 25.98,25.04 25.98,31.52 25.69,31.81 23.85,31.81 23.74,31.92 23.74,32.38 23.85,32.49 25.69,32.49 25.98,32.78 25.98,33.48 25.69,33.76 23.85,33.76 23.74,33.88 23.74,34.33 23.85,34.45 25.69,34.45 25.98,34.73 25.98,36.13 31.08,41.23 31.08,42.79 32.96,44.67 33.1,44.67 U1.38
  BOTTOM w0.114: J1.A2 26.23,20.9 25.98,20.64 25.98,20.1 v2(26.27,19.81)
MIPI_DSI0_DATA0_P: length 43.2
  TOP w0.114: U1.37 32.75,45.03 32.75,44.88 30.78,42.91 30.78,41.35 25.68,36.25 25.68,34.85 25.57,34.74 23.73,34.74 23.44,34.45 23.44,33.75 23.73,33.47 25.57,33.47 25.68,33.35 25.68,32.9 25.57,32.78 23.73,32.78 23.44,32.5 23.44,31.8 23.73,31.51 25.57,31.51 25.68,31.4 25.68,25.17 25.57,25.05 23.86,25.05 23.57,24.77 23.57,24.07 23.86,23.78 25.57,23.78 25.68,23.67 25.68,20.1 v2(25.39,19.81)
  BOTTOM w0.114: J1.A3 25.43,20.9 25.68,20.64 25.68,20.1 v2(25.39,19.81)
MIPI_DSI0_DATA1_N: length 43.4
  TOP w0.114: U1.42 34.52,43.26 34.37,43.26 34.05,42.94 34.05,35.55 35.13,34.47 35.13,25.57 33.34,23.78 33.34,23.62 33.9,23.05 33.9,22.65 33.41,22.15 33,22.15 32.44,22.72 32.28,22.72 31.95,22.4 31.95,22.23 32.52,21.67 32.52,21.27 32.02,20.77 31.62,20.77 31.05,21.34 30.89,21.34 27.86,18.3 23.63,18.3 22.68,19.25 22.51,19.25 v2(22.23,18.97)
  BOTTOM w0.114: J1.A5 23.83,20.9 23.58,20.64 23.58,19.78 23.05,19.25 22.52,19.25 v2(22.23,18.97)
MIPI_DSI0_DATA1_P: length 43.5
  TOP w0.114: U1.41 34.17,43.61 34.17,43.46 33.76,43.06 33.76,35.43 34.84,34.35 34.84,25.69 33.04,23.9 33.04,23.5 33.61,22.93 33.61,22.77 33.29,22.45 33.12,22.45 32.56,23.01 32.16,23.01 31.66,22.52 31.66,22.11 32.23,21.55 32.23,21.39 31.9,21.06 31.74,21.06 31.18,21.63 30.77,21.63 27.74,18.59 23.75,18.59 23.45,18.89 23.45,19.05 23.65,19.25 23.65,19.41 23.48,19.57 23.32,19.57 23.13,19.38 22.97,19.38 22.8,19.55 22.53,19.55 v2(22.23,19.85)
  BOTTOM w0.114: J1.A6 23.03,20.9 23.28,20.64 23.28,19.91 22.92,19.55 22.53,19.55 v2(22.23,19.85)
MIPI_DSI0_DATA2_N: length 43.5
  TOP w0.114: U1.34 31.69,46.09 31.56,46.09 29.84,44.37 28.19,44.37 23.17,39.35 22.76,39.35 22.1,40.01 21.94,40.01 21.61,39.69 21.61,39.53 22.28,38.86 22.28,38.46 21.78,37.96 21.38,37.96 20.71,38.63 20.55,38.63 20.23,38.31 20.23,38.15 20.9,37.48 20.9,37.08 20.4,36.58 20,36.58 19.33,37.25 19.17,37.25 18.84,36.92 18.84,36.76 19.51,36.1 19.51,35.69 18.44,34.62 18.44,34.39 18.23,34.18 18,34.18 17.79,33.97 17.79,33.75 17.59,33.54 17.36,33.54 17.16,33.34 17.16,20.12 v2(17.47,19.81)
  BOTTOM w0.114: v2(17.47,19.81) 17.18,20.1 17.18,20.64 17.43,20.9 J1.A13
MIPI_DSI0_DATA2_P: length 43.5
  TOP w0.114: U1.33 31.34,46.44 31.34,46.28 29.72,44.66 28.07,44.66 23.05,39.64 22.89,39.64 22.22,40.31 21.82,40.31 21.32,39.81 21.32,39.41 21.99,38.74 21.99,38.58 21.66,38.26 21.5,38.26 20.84,38.92 20.43,38.92 19.94,38.43 19.94,38.02 20.6,37.36 20.6,37.2 20.28,36.87 20.12,36.87 19.45,37.54 19.05,37.54 18.55,37.04 18.55,36.64 19.22,35.97 19.22,35.81 16.87,33.46 16.87,20.09 v2(16.59,19.81)
  BOTTOM w0.114: J1.A14 16.63,20.9 16.88,20.64 16.88,20.1 v2(16.59,19.81)
MIPI_DSI0_DATA3_N: length 43.3
  TOP w0.114: U1.36 32.4,45.38 32.25,45.38 21.73,34.86 21.73,24.47 19.42,22.15 19.42,19.61 17.83,18.02 15.17,18.02 13.95,19.25 13.71,19.25 v2(13.43,18.97)
  BOTTOM w0.114: J1.A16 15.03,20.9 14.78,20.64 14.78,19.72 14.31,19.25 13.72,19.25 v2(13.43,18.97)
MIPI_DSI0_DATA3_P: length 43.3
  TOP w0.114: U1.35 32.04,45.73 32.04,45.59 21.44,34.98 21.44,24.59 19.12,22.27 19.12,19.73 17.71,18.32 15.3,18.32 14.72,18.89 14.72,19.05 14.91,19.24 14.91,19.4 14.75,19.56 14.59,19.56 14.4,19.37 14.24,19.37 14.07,19.54 13.74,19.54 v2(13.43,19.85)
  BOTTOM w0.114: v2(13.43,19.85) 13.73,19.55 14.19,19.55 14.48,19.84 14.48,20.64 14.23,20.9 J1.A17
MIPI_DSI0_TS_INT_B: length 55.4
  TOP w0.137: R5.2 v2(26.01,51.44)
  L4_MIX_2 w0.14: v2(20.63,20.66) 21.63,19.66 21.63,18.05 22.06,17.63 25.99,17.63 28.04,19.68 33.09,19.68 v2(33.91,20.5)
  BOTTOM w0.137: v2(26.01,51.44) 25.59,51.02 25.01,51.02 23.99,49.99 23.99,35.03 34.42,24.6 34.42,21.01 v2(33.91,20.5) ; v2(20.63,20.66) J1.A9
MIPI_DSI0_TS_SCL: length 37.6
  BOTTOM w0.137: v1(11.84,38.73) 10.97,38.73 10.39,38.15 10.39,15.95 11.33,15.01 15.05,15.01 19.03,18.99 J1.A11
MIPI_DSI0_TS_SDA: length 41
  BOTTOM w0.137: v1(11.84,41.27) 11.84,40.04 10.07,38.28 10.07,15.82 11.2,14.7 15.18,14.7 19.83,19.35 J1.A10
MIPI_DSI1_1_EN: length 47.8
  TOP w0.137: v2(32.05,28.8) 32.26,29.01 U2.2 ; R81.2 v2(26.9,52.25)
  L3_MIX_1 w0.14: v2(32.05,28.8) 43.33,28.8 v2(43.94,28.19)
  BOTTOM w0.137: J2.B11 44.69,28.19 R72.1 v2(43.94,28.19) ; v2(26.9,52.25) 26.9,50.9 25.74,49.74 25.74,47.66 24.83,46.75 24.83,35.12 31.15,28.8 v2(32.05,28.8)
MIPI_DSI1_BL_PWM: length 54.8
  TOP w0.137: R6.2 v2(24.8,49.89)
  L4_MIX_2 w0.14: v2(35.05,19.43) 35.6,18.88 35.6,16.47 35.65,16.42 35.65,16.27 36.96,14.96 41.4,14.96 v2(46.19,19.75)
  BOTTOM w0.137: v2(35.05,19.43) 35.05,24.41 24.3,35.16 24.3,49.39 v2(24.8,49.89) ; v2(46.19,19.75) 46.69,20.25 J2.A8
MIPI_DSI1_CLK_N: length 63.9
  TOP w0.114: v2(51.93,26.66) 51.64,26.96 51.64,30.89 51.04,31.48 50.61,31.48 50.5,31.6 50.5,32.43 50.22,32.72 49.52,32.72 49.23,32.43 49.23,31.6 49.12,31.48 48.66,31.48 48.54,31.6 48.54,33.8 48.24,34.11 47.56,34.11 47.27,33.82 47.27,31.62 47.14,31.48 46.75,31.48 46.64,31.6 46.64,33.8 46.33,34.11 45.65,34.11 45.32,33.78 45.32,31.6 45.2,31.48 44.75,31.48 44.63,31.6 44.63,32.28 44.35,32.56 43.65,32.56 43.36,32.28 43.36,31.6 43.25,31.48 42.06,31.48 41.83,31.71 41.83,31.87 43.36,33.4 43.36,33.83 42.9,34.29 42.45,34.29 40.93,32.77 40.77,32.77 40.45,33.09 40.45,33.25 41.82,34.63 41.82,35.04 41.39,35.47 40.86,35.47 39.55,34.15 39.39,34.15 38.9,34.64 38.9,35.89 39.01,36.01 40.66,36.01 40.96,36.31 40.96,36.99 40.68,37.28 39.01,37.28 38.9,37.39 38.9,37.85 39.01,37.96 40.66,37.96 40.95,38.25 40.95,38.95 40.66,39.23 39.01,39.23 38.9,39.35 38.9,39.8 39.01,39.92 40.15,39.92 40.44,40.2 40.44,40.9 40.15,41.19 39.01,41.19 38.9,41.3 38.9,42.93 37.66,44.17 37.66,44.32 37.13,44.85
  BOTTOM w0.114: v2(51.93,26.66) 51.64,26.37 51.64,25.83 51.89,25.57 J2.B2
MIPI_DSI1_CLK_P: length 64
  TOP w0.114: v2(51.05,26.66) 51.35,26.96 51.35,27.37 51.19,27.52 51.19,27.83 51.35,27.98 51.35,28.28 51.19,28.44 51.19,28.74 51.35,28.89 51.35,30.76 50.92,31.19 50.49,31.19 50.21,31.48 50.21,32.31 50.09,32.43 49.64,32.43 49.52,32.31 49.52,31.48 49.24,31.19 48.54,31.19 48.25,31.48 48.25,33.68 48.11,33.82 47.68,33.82 47.57,33.7 47.57,31.48 47.28,31.19 46.58,31.19 46.3,31.48 46.3,33.71 46.18,33.82 45.78,33.82 45.61,33.65 45.61,31.48 45.33,31.19 44.63,31.19 44.34,31.48 44.34,32.16 44.23,32.27 43.77,32.27 43.66,32.16 43.66,31.48 43.37,31.19 41.94,31.19 41.54,31.59 41.54,31.99 43.07,33.52 43.07,33.71 42.78,34 42.57,34 41.05,32.48 40.65,32.48 40.15,32.97 40.15,33.38 41.53,34.75 41.53,34.91 41.27,35.18 40.98,35.18 39.67,33.86 39.27,33.86 38.61,34.52 38.61,36.01 38.89,36.3 40.54,36.3 40.67,36.43 40.67,36.87 40.56,36.98 38.89,36.98 38.61,37.27 38.61,37.97 38.89,38.25 40.54,38.25 40.66,38.37 40.66,38.83 40.54,38.94 38.89,38.94 38.61,39.23 38.61,39.92 38.89,40.21 40.03,40.21 40.14,40.32 40.14,40.78 40.03,40.9 38.89,40.9 38.61,41.18 38.61,42.81 37.46,43.96 37.31,43.96 U1.45
  BOTTOM w0.114: J2.B3 51.09,25.57 51.35,25.83 51.35,26.37 v2(51.05,26.66)
